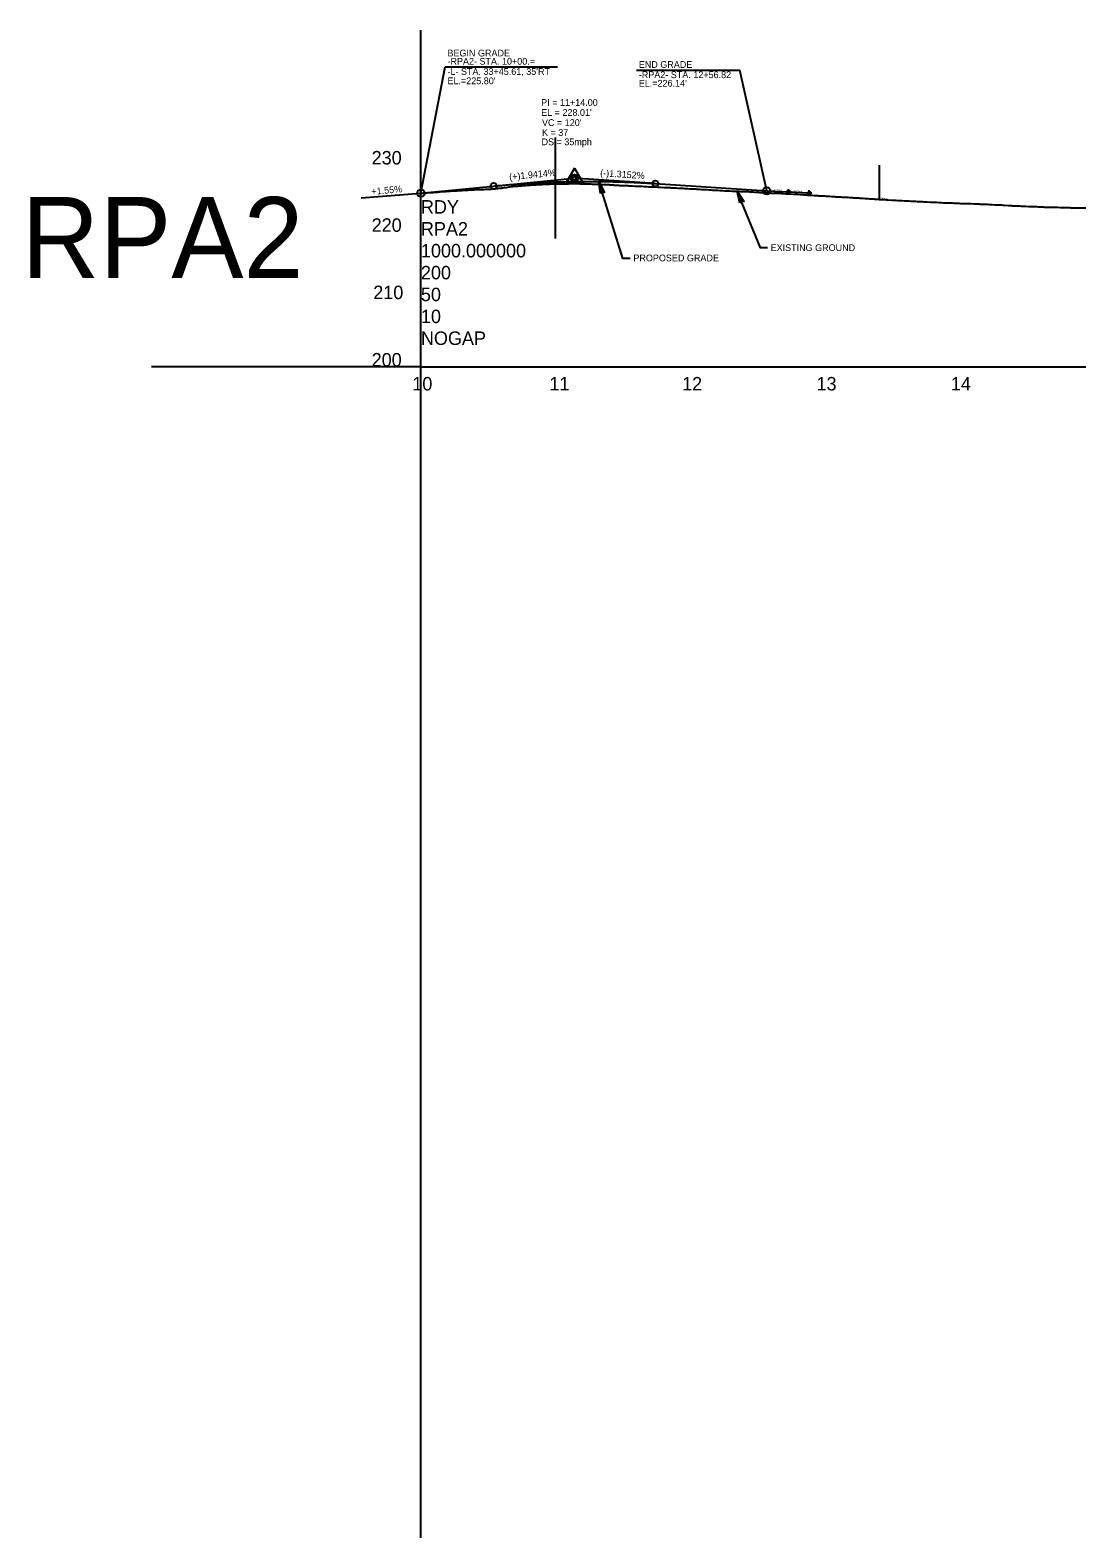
# Model space of a CAD drawing. Extents: x 2115752 to 2121174, y 562881 to 567245.
# Drawn here: x 2117413 to 2118197, y 564637 to 565756 of the extents above; entities that cross this region are included whole.
import ezdxf

# ---------------------------------------------------------------- set-up
doc = ezdxf.new("R2010")
doc.units = 0
for name, color, linetype in [('Exist Profile Cell', 7, 'Continuous'), ('Exist Vertical Profile Ground Line', 7, 'Continuous'), ('Exist Vertical Profile Horizontal Axis Label Major', 7, 'Continuous'), ('Exist Vertical Profile Vertical Axis Label', 7, 'Continuous'), ('Prop PFL VPI Symbol CELL', 7, 'Continuous'), ('Prop Terminator CELL', 7, 'Continuous'), ('Prop Vertical Profile Curve Label', 7, 'Continuous'), ('Prop Vertical Profile Grade', 7, 'Continuous'), ('Prop Vertical Profile Grade Label', 7, 'Continuous'), ('Prop VPI Label', 7, 'Continuous'), ('Scratch_Level_1', 7, 'Continuous')]:
    doc.layers.add(name, color=color, linetype=linetype)

msp = doc.modelspace()

# ---------------------------------------------------------------- linework, layer by layer
at = {"layer": 'Exist Profile Cell'}
for q in [(2117703.5, 565756.4), (2118197.3, 565506.4), (2117703.5, 565506.4)]:
    msp.add_line((2117703.5, 565506.4), q, dxfattribs=at)
at = {"layer": 'Exist Vertical Profile Ground Line'}
for points in [[(2117703.5, 565635.4), (2117704.4, 565635.5), (2117704.9, 565635.5), (2117705.3, 565635.6), (2117706.1, 565635.6), (2117707, 565635.7), (2117708.2, 565635.7), (2117708.7, 565635.8), (2117709.7, 565635.8), (2117710.5, 565635.9), (2117711.6, 565636), (2117712.4, 565636), (2117713.1, 565636.1), (2117714, 565636.1), (2117714.8, 565636.2), (2117715.7, 565636.2), (2117716.6, 565636.3), (2117717, 565636.4), (2117717.6, 565636.4), (2117718.3, 565636.5), (2117718.6, 565636.5), (2117719.2, 565636.5), (2117720.1, 565636.6), (2117720.5, 565636.6), (2117721, 565636.6), (2117721.9, 565636.7), (2117722.9, 565636.8), (2117723.5, 565636.8), (2117724.4, 565636.9), (2117725.3, 565636.9), (2117726.3, 565637), (2117727.2, 565637), (2117727.9, 565637.1), (2117729, 565637.1), (2117729.6, 565637.2), (2117730.5, 565637.2), (2117731.4, 565637.3), (2117731.8, 565637.3), (2117732.2, 565637.3), (2117733.2, 565637.4), (2117734, 565637.4), (2117734.5, 565637.5), (2117734.9, 565637.5), (2117735.3, 565637.5), (2117735.7, 565637.5), (2117736.6, 565637.6), (2117737.2, 565637.6), (2117737.5, 565637.6), (2117738, 565637.7), (2117738.3, 565637.7), (2117739.2, 565637.8), (2117739.8, 565637.8), (2117740.3, 565637.8), (2117741, 565637.8), (2117742, 565637.9), (2117742.7, 565637.9), (2117743.6, 565638), (2117744.4, 565638), (2117745.3, 565638), (2117746.2, 565638), (2117747.2, 565638.1), (2117747.9, 565638.1), (2117748.8, 565638.1), (2117749.3, 565638.1), (2117749.7, 565638.1), (2117750.2, 565638.1), (2117750.5, 565638.2), (2117751.4, 565638.3), (2117752.3, 565638.3), (2117752.7, 565638.3), (2117753.2, 565638.3), (2117753.5, 565638.3), (2117754, 565638.4), (2117754.9, 565638.4), (2117755.3, 565638.4), (2117755.8, 565638.5), (2117756.8, 565638.6), (2117757.5, 565638.6), (2117757.8, 565638.6), (2117758.6, 565638.7), (2117759.3, 565638.8), (2117760.3, 565638.9), (2117761, 565639), (2117761.9, 565639.1), (2117762.4, 565639.1), (2117762.8, 565639.2), (2117763.1, 565639.2), (2117763.6, 565639.3), (2117764.5, 565639.4), (2117765.5, 565639.5), (2117766.2, 565639.6), (2117767.1, 565639.7), (2117768, 565639.8), (2117768.8, 565640), (2117769.2, 565640), (2117769.7, 565640.1), (2117770.8, 565640.3), (2117771.5, 565640.4), (2117772.3, 565640.5), (2117772.9, 565640.5), (2117773.2, 565640.6)], [(2117773.2, 565640.6), (2117774.1, 565640.6), (2117775.4, 565640.7), (2117775.8, 565640.8), (2117776.7, 565640.8), (2117778.2, 565640.9), (2117778.9, 565641), (2117780.1, 565641.1), (2117780.4, 565641.1), (2117781.2, 565641.2), (2117782.3, 565641.3), (2117782.9, 565641.3), (2117783.5, 565641.4), (2117784.6, 565641.4), (2117785.7, 565641.5), (2117787, 565641.6), (2117788, 565641.6), (2117789.2, 565641.6), (2117790.4, 565641.7), (2117791.3, 565641.8), (2117792.5, 565641.8), (2117793.6, 565641.9), (2117794.7, 565642), (2117795, 565642), (2117795.5, 565642), (2117795.8, 565642), (2117797.3, 565642.1), (2117798.1, 565642.1), (2117799.2, 565642.1), (2117800.6, 565642.2), (2117801.5, 565642.2), (2117802.6, 565642.2), (2117803.2, 565642.3), (2117803.7, 565642.3), (2117804.9, 565642.3), (2117806, 565642.3), (2117807.1, 565642.4), (2117808.5, 565642.4), (2117809, 565642.4), (2117809.4, 565642.4), (2117810.5, 565642.4), (2117810.9, 565642.4), (2117811.6, 565642.4), (2117812.8, 565642.4), (2117813.5, 565642.5), (2117813.9, 565642.5), (2117814.5, 565642.5), (2117815, 565642.5), (2117816.1, 565642.5), (2117817.3, 565642.5), (2117818.1, 565642.5), (2117818.4, 565642.5), (2117818.7, 565642.5), (2117819.5, 565642.5), (2117820.6, 565642.5), (2117821.3, 565642.5), (2117821.8, 565642.4), (2117823, 565642.4), (2117824, 565642.4), (2117824.4, 565642.4), (2117825.2, 565642.3), (2117825.8, 565642.3), (2117826.7, 565642.3), (2117827.4, 565642.3), (2117828.5, 565642.2), (2117829.3, 565642.2), (2117829.7, 565642.2), (2117830.8, 565642.1), (2117832.2, 565642.1), (2117832.6, 565642.1), (2117833, 565642), (2117834.2, 565642), (2117834.7, 565642), (2117835.3, 565642), (2117836.4, 565641.9), (2117837.8, 565641.9), (2117838.8, 565641.9), (2117839.8, 565641.8), (2117840.2, 565641.8), (2117840.9, 565641.7), (2117841.6, 565641.7), (2117842.1, 565641.7), (2117843.2, 565641.7), (2117843.8, 565641.6), (2117844.5, 565641.6), (2117845.4, 565641.5), (2117845.8, 565641.5), (2117846.6, 565641.5), (2117847.2, 565641.4), (2117847.7, 565641.4), (2117848.4, 565641.4), (2117848.8, 565641.4), (2117849.3, 565641.3), (2117850, 565641.3), (2117850.8, 565641.3), (2117851.1, 565641.2), (2117852.4, 565641.2), (2117853.3, 565641.2), (2117853.9, 565641.1), (2117854.5, 565641.1), (2117855.2, 565641.1)], [(2117855.2, 565641.1), (2117855.6, 565641), (2117856.7, 565641), (2117857.2, 565641), (2117857.8, 565640.9), (2117859, 565640.9), (2117859.7, 565640.8), (2117860.3, 565640.8), (2117860.7, 565640.8), (2117862.7, 565640.7), (2117863.3, 565640.7), (2117864.5, 565640.7), (2117865.4, 565640.6), (2117865.9, 565640.6), (2117867.9, 565640.5), (2117869.1, 565640.4), (2117870.5, 565640.3), (2117871.4, 565640.3), (2117872.8, 565640.2), (2117873.1, 565640.2), (2117873.8, 565640.2), (2117874.5, 565640.1), (2117875, 565640.1), (2117875.7, 565640.1), (2117876.1, 565640.1), (2117877.4, 565640), (2117878.3, 565640), (2117879.7, 565639.9), (2117880.9, 565639.8), (2117881.3, 565639.8), (2117883.8, 565639.7), (2117885.8, 565639.6), (2117886.2, 565639.6), (2117886.6, 565639.6), (2117887.9, 565639.5), (2117888.3, 565639.5), (2117888.8, 565639.5), (2117889.1, 565639.4), (2117889.6, 565639.4), (2117891.4, 565639.4), (2117892.4, 565639.3), (2117893.1, 565639.3), (2117894.2, 565639.2), (2117895, 565639.2), (2117896.6, 565639.1), (2117898.3, 565639), (2117899.3, 565638.9), (2117900.5, 565638.8), (2117901.8, 565638.8), (2117903.3, 565638.7), (2117904, 565638.6), (2117904.6, 565638.6), (2117906.2, 565638.5), (2117907.1, 565638.5), (2117907.6, 565638.5), (2117908.4, 565638.4), (2117909.2, 565638.4), (2117909.8, 565638.3), (2117910.6, 565638.3), (2117912.2, 565638.2), (2117912.9, 565638.1), (2117913.5, 565638.1), (2117914.8, 565638), (2117915.5, 565638), (2117915.8, 565638), (2117917.4, 565637.9), (2117918.4, 565637.8), (2117918.7, 565637.8), (2117920, 565637.7), (2117921.2, 565637.7), (2117922.6, 565637.6), (2117924, 565637.5), (2117925.4, 565637.4), (2117926.5, 565637.4), (2117927.4, 565637.3), (2117927.8, 565637.3), (2117929.3, 565637.2), (2117929.7, 565637.2), (2117930.4, 565637.2), (2117931.4, 565637.1), (2117933, 565637), (2117934.6, 565636.9), (2117935.3, 565636.9), (2117935.6, 565636.9), (2117936.1, 565636.9), (2117938.3, 565636.8), (2117939, 565636.8), (2117940.1, 565636.8), (2117940.9, 565636.7), (2117942.2, 565636.7), (2117943.8, 565636.6), (2117944.6, 565636.6), (2117945.6, 565636.5), (2117946.1, 565636.5), (2117946.6, 565636.5), (2117947.5, 565636.4), (2117948.7, 565636.4), (2117949.3, 565636.3), (2117950, 565636.3), (2117951.3, 565636.2), (2117951.8, 565636.2)], [(2117951.8, 565636.2), (2117952.1, 565636.2), (2117953.9, 565636.1), (2117954.9, 565636), (2117955.4, 565636), (2117956.5, 565635.9), (2117956.8, 565635.9), (2117957.4, 565635.8), (2117957.7, 565635.8), (2117959.3, 565635.8), (2117960.5, 565635.7), (2117961, 565635.7), (2117961.7, 565635.6), (2117962.5, 565635.6), (2117963.3, 565635.5), (2117964.3, 565635.5), (2117964.9, 565635.5), (2117966.1, 565635.5), (2117966.4, 565635.5), (2117966.9, 565635.4), (2117968.3, 565635.4), (2117968.8, 565635.4), (2117969.5, 565635.3), (2117970.5, 565635.3), (2117971.6, 565635.2), (2117972.1, 565635.2), (2117972.6, 565635.2), (2117974.7, 565635), (2117977.3, 565634.9), (2117977.7, 565634.9), (2117980.2, 565634.7), (2117982.6, 565634.6), (2117983.1, 565634.6), (2117985.1, 565634.4), (2117985.5, 565634.4), (2117986.3, 565634.3), (2117987.7, 565634.2), (2117988.1, 565634.2), (2117989.4, 565634.2), (2117990.3, 565634.1), (2117990.9, 565634), (2117991.5, 565634), (2117992.4, 565633.9), (2117993, 565633.9), (2117993.5, 565633.8), (2117994.4, 565633.8), (2117995.6, 565633.7), (2117996.3, 565633.7), (2117997, 565633.6), (2117998.2, 565633.6), (2117999, 565633.5), (2118000.8, 565633.4), (2118001.7, 565633.4), (2118002.2, 565633.4), (2118003.4, 565633.3), (2118004.5, 565633.2), (2118005.1, 565633.2), (2118006, 565633.2), (2118007.1, 565633.1), (2118008.6, 565633), (2118010, 565632.9), (2118011.2, 565632.8), (2118011.5, 565632.7), (2118012.5, 565632.7), (2118013.8, 565632.6), (2118014.2, 565632.6), (2118015.3, 565632.6), (2118016.4, 565632.5), (2118018.1, 565632.4), (2118019, 565632.4), (2118019.9, 565632.3), (2118020.6, 565632.3), (2118021.7, 565632.2), (2118023.2, 565632.1), (2118023.6, 565632.1), (2118024.2, 565632.1), (2118024.8, 565632), (2118026, 565631.9), (2118026.8, 565631.9), (2118027.6, 565631.9), (2118028.9, 565631.8), (2118029.4, 565631.7), (2118030, 565631.7), (2118031.7, 565631.6), (2118032, 565631.6), (2118033.4, 565631.5), (2118034.1, 565631.4), (2118034.6, 565631.4), (2118035.4, 565631.4), (2118036.6, 565631.3), (2118037.5, 565631.2), (2118038.7, 565631.1), (2118039.4, 565631.1), (2118039.8, 565631.1), (2118040.7, 565631), (2118041.7, 565630.9), (2118042.1, 565630.9), (2118042.4, 565630.9), (2118043, 565630.9), (2118044.5, 565630.8), (2118045.2, 565630.7)], [(2118045.2, 565630.7), (2118045.8, 565630.7), (2118047, 565630.6), (2118047.4, 565630.6), (2118048, 565630.6), (2118049.2, 565630.5), (2118050.5, 565630.4), (2118053, 565630.3), (2118055.7, 565630.1), (2118056.1, 565630.1), (2118057.4, 565630), (2118058.2, 565630), (2118059.4, 565629.9), (2118060.2, 565629.9), (2118060.8, 565629.9), (2118062.6, 565629.8), (2118063.2, 565629.7), (2118064.9, 565629.7), (2118065.8, 565629.6), (2118067, 565629.5), (2118067.8, 565629.5), (2118068.2, 565629.5), (2118068.9, 565629.4), (2118070.2, 565629.4), (2118070.7, 565629.4), (2118072.1, 565629.3), (2118073.2, 565629.2), (2118074.3, 565629.2), (2118075.3, 565629.1), (2118075.7, 565629.1), (2118077, 565629), (2118077.5, 565629), (2118078.5, 565629), (2118079.5, 565628.9), (2118082, 565628.8), (2118084, 565628.7), (2118085, 565628.6), (2118086.4, 565628.6), (2118088.2, 565628.5), (2118088.9, 565628.4), (2118090.2, 565628.4), (2118091.6, 565628.3), (2118093.4, 565628.3), (2118094.1, 565628.2), (2118094.6, 565628.2), (2118095.9, 565628.1), (2118096.3, 565628.1), (2118098.1, 565628.1), (2118099.3, 565628), (2118101, 565628), (2118101.6, 565627.9), (2118103.3, 565627.9), (2118104.2, 565627.8), (2118106, 565627.8), (2118107.4, 565627.7), (2118108.1, 565627.7), (2118109.2, 565627.7), (2118110.6, 565627.6), (2118111, 565627.6), (2118111.8, 565627.6), (2118114.2, 565627.5), (2118115.9, 565627.4), (2118116.7, 565627.4), (2118117.1, 565627.4), (2118118.2, 565627.4), (2118118.9, 565627.3), (2118119.7, 565627.3), (2118120.3, 565627.3), (2118121.5, 565627.2), (2118122.4, 565627.2), (2118123.6, 565627.1), (2118124.2, 565627.1), (2118125.8, 565627), (2118126.7, 565627), (2118127.7, 565626.9), (2118129.4, 565626.8), (2118129.9, 565626.8), (2118130.9, 565626.8), (2118131.9, 565626.7), (2118132.4, 565626.7), (2118133.1, 565626.7), (2118134.6, 565626.6), (2118135.7, 565626.5), (2118136.3, 565626.5), (2118137.2, 565626.4), (2118139.9, 565626.3), (2118142.4, 565626.2), (2118142.8, 565626.1), (2118143.7, 565626.1), (2118145, 565626), (2118146, 565626), (2118147.8, 565625.9), (2118148.3, 565625.9), (2118149.2, 565625.8), (2118149.8, 565625.8), (2118150.2, 565625.8), (2118151, 565625.8), (2118152.4, 565625.7), (2118152.8, 565625.7), (2118154.7, 565625.6), (2118155.9, 565625.6)], [(2118155.9, 565625.6), (2118157.3, 565625.5), (2118158, 565625.5), (2118158.8, 565625.4), (2118159.9, 565625.4), (2118160.6, 565625.4), (2118162, 565625.3), (2118163.2, 565625.3), (2118164, 565625.2), (2118165.2, 565625.2), (2118166, 565625.2), (2118166.6, 565625.1), (2118168, 565625.1), (2118168.4, 565625.1), (2118169.1, 565625.1), (2118171, 565625), (2118171.7, 565625), (2118172.1, 565625), (2118173.6, 565624.9), (2118174.1, 565624.9), (2118174.9, 565624.9), (2118176.2, 565624.9), (2118178.2, 565624.8), (2118178.8, 565624.8), (2118179.7, 565624.8), (2118181.4, 565624.8), (2118183.3, 565624.7), (2118184, 565624.7), (2118184.5, 565624.7), (2118185.8, 565624.7), (2118186.5, 565624.6), (2118187.7, 565624.6), (2118188.4, 565624.6), (2118189.1, 565624.6), (2118190.2, 565624.6), (2118190.9, 565624.6), (2118191.7, 565624.6), (2118193.7, 565624.5), (2118194.3, 565624.5), (2118194.6, 565624.5), (2118195.9, 565624.5), (2118196.9, 565624.5), (2118197.3, 565624.5)]]:
    msp.add_lwpolyline(points, dxfattribs=at)
at = {"layer": 'Prop PFL VPI Symbol CELL'}
for p, q in [((2117817.5, 565654), (2117811, 565642.8)), ((2117817.5, 565654), (2117824, 565642.8)), ((2117811, 565642.8), (2117824, 565642.8))]:
    msp.add_line(p, q, dxfattribs=at)
for radius in [1.75, 1.2]:
    msp.add_circle((2117817.5, 565646.5), radius, dxfattribs=at)
at = {"layer": 'Prop Terminator CELL'}
for points in [[(2117836.9, 565635.1), (2117835.6, 565644.1), (2117839.9, 565635.9), (2117838, 565636.6)], [(2117940.3, 565627.9), (2117938.3, 565636.8), (2117943.2, 565629.1), (2117941.3, 565629.5)]]:
    msp.add_lwpolyline(points, close=True, dxfattribs=at)
at = {"layer": 'Prop Vertical Profile Curve Label'}
for centre in [(2117757.5, 565640.7), (2117877.5, 565642.5)]:
    msp.add_circle(centre, 2.25, dxfattribs=at)
at = {"layer": 'Prop Vertical Profile Grade'}
for p, q in [((2117703.5, 565635.4), (2117757.5, 565640.7)), ((2117877.5, 565642.5), (2117960.3, 565637.1))]:
    msp.add_line(p, q, dxfattribs=at)
msp.add_spline([(2117757.5, 565640.7), (2117759.9, 565640.9), (2117762.3, 565641.1), (2117764.7, 565641.3), (2117767.1, 565641.5), (2117769.5, 565641.7), (2117771.9, 565641.9), (2117774.3, 565642.1), (2117776.7, 565642.3), (2117779.1, 565642.4), (2117781.5, 565642.6), (2117783.9, 565642.8), (2117786.3, 565642.9), (2117788.7, 565643), (2117791.1, 565643.2), (2117793.5, 565643.3), (2117795.9, 565643.4), (2117798.3, 565643.5), (2117800.7, 565643.6), (2117803.1, 565643.7), (2117805.5, 565643.8), (2117807.9, 565643.8), (2117810.3, 565643.9), (2117812.7, 565644), (2117815.1, 565644), (2117817.5, 565644), (2117819.9, 565644.1), (2117822.3, 565644.1), (2117824.7, 565644.1), (2117827.1, 565644.1), (2117829.5, 565644.1), (2117831.9, 565644.1), (2117834.3, 565644.1), (2117836.7, 565644.1), (2117839.1, 565644.1), (2117841.5, 565644), (2117843.9, 565644), (2117846.3, 565643.9), (2117848.7, 565643.9), (2117851.1, 565643.8), (2117853.5, 565643.7), (2117855.9, 565643.6), (2117858.3, 565643.6), (2117860.7, 565643.5), (2117863.1, 565643.3), (2117865.5, 565643.2), (2117867.9, 565643.1), (2117870.3, 565643), (2117872.7, 565642.8), (2117875.1, 565642.7), (2117877.5, 565642.5)], degree=3, dxfattribs=at)
at = {"layer": 'Prop VPI Label'}
for p, q in [((2117703.5, 565635.4), (2117721.4, 565729.2)), ((2117721.4, 565729.2), (2117804.9, 565729.2)), ((2117863.6, 565726.7), (2117940.3, 565726.7)), ((2117960.3, 565637.1), (2117940.3, 565726.7)), ((2117757.5, 565640.7), (2117814.8, 565646.2)), ((2117877.5, 565642.5), (2117820.2, 565646.3)), ((2117659.1, 565632), (2117703.5, 565635.4))]:
    msp.add_line(p, q, dxfattribs=at)
for points in [[(2117858.8, 565586.9), (2117853.5, 565586.9), (2117835.6, 565644.1)], [(2117960.8, 565594.7), (2117955.8, 565594.7), (2117938.3, 565636.8)]]:
    msp.add_lwpolyline(points, dxfattribs=at)
for centre in [(2117817.5, 565646.5), (2117960.3, 565637.1), (2117703.5, 565635.4)]:
    msp.add_circle(centre, 2.75, dxfattribs=at)
at = {"layer": 'Scratch_Level_1'}
for p, q in [((2117803.5, 565601.7), (2117803.5, 565676.6)), ((2118043.8, 565656.2), (2118043.8, 565630.8)), ((2117960.3, 565637.1), (2117976.5, 565636.4)), ((2117974.6, 565636.4), (2117976.5, 565636.4)), ((2117976.5, 565636.4), (2117976.5, 565638.4)), ((2117976.5, 565636.4), (2117978.5, 565636.4)), ((2117976.5, 565634.5), (2117976.5, 565636.4)), ((2117976.5, 565636.4), (2117991.9, 565635.7)), ((2117989.9, 565635.7), (2117991.9, 565635.7)), ((2117991.9, 565635.7), (2117991.9, 565637.6)), ((2117991.9, 565635.7), (2117993.8, 565635.7)), ((2117991.9, 565633.8), (2117991.9, 565635.7)), ((2118043.8, 565630.8), (2118045.2, 565630.7)), ((2118043.8, 565630.8), (2118048, 565630.6)), ((2117703.5, 565506.4), (2117503.5, 565506.4)), ((2117703.5, 564637), (2117703.5, 565506.4))]:
    msp.add_line(p, q, dxfattribs=at)
for centre in [(2117976.5, 565636.4), (2117991.9, 565635.7)]:
    msp.add_circle(centre, 0.949, dxfattribs=at)

# ---------------------------------------------------------------- texts
at = {"layer": 'Exist Profile Cell'}
for s, p in [('RDY', (2117703.5, 565620.2)), ('RPA2', (2117703.5, 565603.9)), ('1000.000000', (2117703.5, 565587.7)), ('200', (2117703.5, 565571.4)), ('50', (2117703.5, 565555.2)), ('10', (2117703.5, 565538.9)), ('NOGAP', (2117703.5, 565522.7))]:
    msp.add_text(s, height=10, dxfattribs=at).set_placement(p)
at = {"layer": 'Exist Vertical Profile Horizontal Axis Label Major'}
for s, p in [('10', (2117697.1, 565488.9)), ('11', (2117798.9, 565488.9)), ('12', (2117897.5, 565488.9)), ('13', (2117997.3, 565488.9)), ('14', (2118097.1, 565488.9))]:
    msp.add_text(s, height=10, dxfattribs=at).set_placement(p)
at = {"layer": 'Exist Vertical Profile Vertical Axis Label'}
for s, height, p in [('230', 10, (2117666.9, 565656.7)), ('RPA2', 60, (2117406.7, 565572.5)), ('220', 10, (2117666.9, 565606.7)), ('210', 10, (2117668.1, 565556.7)), ('200', 10, (2117666.9, 565506.7))]:
    msp.add_text(s, height=height, dxfattribs=at).set_placement(p)
at = {"layer": 'Prop Vertical Profile Curve Label'}
for s, p in [("VC = 120'", (2117793.4, 565685.3)), ('DS = 35mph', (2117793.1, 565671)), ('K = 37', (2117793.4, 565677.9))]:
    msp.add_text(s, height=5, dxfattribs=at).set_placement(p)
at = {"layer": 'Prop Vertical Profile Grade Label'}
for s, rotation, p in [('(+)1.9414%', 5.5444, (2117769.3, 565645)), ('(-)1.3152%', 356.2377, (2117836.5, 565648)), ('+1.55%', 5.0015, (2117666.9, 565634.1))]:
    msp.add_text(s, height=5, rotation=rotation, dxfattribs=at).set_placement(p)
at = {"layer": 'Prop VPI Label'}
for s, p in [('BEGIN GRADE', (2117723.2, 565736.9)), ('-RPA2- STA. 10+00.=', (2117723.2, 565730.8)), ('END GRADE', (2117865.3, 565728.4)), ("-L- STA. 33+45.61, 35'RT", (2117723.2, 565723.2)), ("EL.=225.80'", (2117723.2, 565716.3)), ('-RPA2- STA. 12+56.82', (2117865.3, 565720.8)), ("EL.=226.14'", (2117865.3, 565714.5)), ('PI = 11+14.00', (2117792.8, 565700.2)), ("EL = 228.01'", (2117792.8, 565692.8)), ('EXISTING GROUND', (2117963.2, 565592.4)), ('PROPOSED GRADE', (2117861.3, 565584.8))]:
    msp.add_text(s, height=5, dxfattribs=at).set_placement(p)
at = {"layer": 'Scratch_Level_1'}
for s, rotation, p in [('-0.8180 %', 357.6579, (2117965.2, 565637.3)), ('-0.9564 %', 357.2623, (2117980.3, 565636.6)), ('-1.2514 %', 356.4197, (2118044, 565631.1))]:
    msp.add_text(s, height=1, rotation=rotation, dxfattribs=at).set_placement(p)

doc.saveas('drawing.dxf')
